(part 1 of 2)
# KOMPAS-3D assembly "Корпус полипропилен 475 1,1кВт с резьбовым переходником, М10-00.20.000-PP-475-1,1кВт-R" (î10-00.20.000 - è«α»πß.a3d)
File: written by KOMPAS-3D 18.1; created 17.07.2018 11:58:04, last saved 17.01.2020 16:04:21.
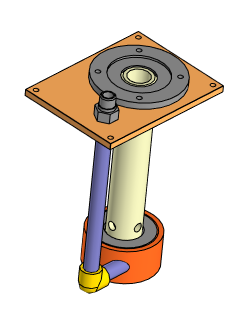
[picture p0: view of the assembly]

Document properties: Автор: Милов; Полное имя файла: C:\Users\User\Desktop\Магна 10 для Караби\М10-00.20.000 - Корпус.a3d

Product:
- Part/product: Корпус полипропилен 475 1,1кВт с резьбовым переходником  | designation М10-00.20.000-PP-475-1,1кВт-R
    Материал: Полипропилен  ГОСТ 26996-86 (density 900 kg/m3)
    Масса: 5.23433
  - Component [detail]: Переходник с пластмассовой резьбой  / наружной 32х1" FV PPR  / ф. "FV PLAST"  | pos. 10  | Масса: 0.0328755; Раздел спецификации: Прочие изделия; source file: D:\1 ПКИ 3D\Полипропиленовые фитинги, трубы\Переходник с пластмассовой резьбой наружной 32х1 FV PPR ф.FV Plast.m3d
  - Component [detail]: Фланец  | designation М10-00.20.002  | pos. 5
      Материал: Полипропилен  ГОСТ 26996-86 (density 900 kg/m3)
      Масса: 0.439491
      Раздел спецификации: Детали
      Форматы листов документа: A3
      Примечание: габ. 71, 80
      source file: М10-00.20.002 - Фланец.cdw, М10-00.20.002 - Фланец.m3d
  - Component [detail]: Колонна  | designation М10-00.25.001-PP-475  | pos. 6  | Масса: 2.126; Раздел спецификации: Детали; Форматы листов документа: A4; source file: М10-00.25.001 - Колонна.m3d
  - Component [detail]: Труба 32 PN10 S=2,9 FV PPR ф. "FV PLAST"  | pos. 12  | Материал: Труба 32 PN10 S=2,9 FV PPR ф. "FV PLAST" (density 0 kg/m3); Раздел спецификации: Материалы; Примечание: мм; source file: Труба 32 PN10 S=2,9 FV PPR ф. FV PLAST.m3d
  - Component [detail]: Колено 90@1~ @2~40FV PPR ф. "FV PLAST"  | pos. 9  | Масса: 0.141726; Раздел спецификации: Прочие изделия; source file: Колено 90гр 32 FV PPR ф. FV PLAST.m3d
  - Component [detail]: Плита опорная  | designation М10-00.20.001-01  | pos. 4  | Масса: 1.84628; Раздел спецификации: Детали; Форматы листов документа: A3; source file: М10-00.20.001 - Плита опорная.m3d
  - Component [assembly]: Обечайка  | designation М10-00.30.000  | pos. 1  | Материал: Полипропилен  ГОСТ 26996-86 (density 900 kg/m3); Масса: 0.647968; Раздел спецификации: Сборочные единицы; Форматы листов документа: A3; source file: М10-00.30.000 - Обечайка.a3d, М10-00.30.000 - Обечайка.cdw
- Part/product: Корпус полипропилен 475 1,1кВт с разъёмной муфтой  | designation М10-00.20.000-PP-475-1,1кВт-M
    Материал: Полипропилен  ГОСТ 26996-86 (density 900 kg/m3)
    Масса: 6.15084
  - Component [detail]: Муфта разъёмная 32  | pos. 7  | Масса: 0.949384; Раздел спецификации: Детали; source file: D:\1 ПКИ 3D\Полипропиленовые фитинги, трубы\Разборные муфты\Муфта разъёмная 32.m3d
  - Component [detail]: Фланец  | designation М10-00.20.002
      Материал: Полипропилен  ГОСТ 26996-86 (density 900 kg/m3)
      Масса: 0.439491
      Раздел спецификации: Детали
      Форматы листов документа: A3
      Примечание: габ. 71, 80
      source file: М10-00.20.002 - Фланец.cdw, М10-00.20.002 - Фланец.m3d
  - Component [detail]: Фланец  | designation М10-00.20.002  | pos. 5
      Материал: Полипропилен  ГОСТ 26996-86 (density 900 kg/m3)
      Масса: 0.439491
      Раздел спецификации: Детали
      Форматы листов документа: A3
      Примечание: габ. 71, 80
      source file: М10-00.20.002 - Фланец.cdw, М10-00.20.002 - Фланец.m3d
  - Component [detail]: Колонна  | designation М10-00.25.001-PP-475  | pos. 6  | Масса: 2.126; Раздел спецификации: Детали; Форматы листов документа: A4; source file: М10-00.25.001 - Колонна.m3d
  - Component [detail]: Труба 32 PN10 S=2,9 FV PPR ф. "FV PLAST"  | pos. 12  | Материал: Труба 32 PN10 S=2,9 FV PPR ф. "FV PLAST" (density 0 kg/m3); Раздел спецификации: Материалы; Примечание: мм; source file: Труба 32 PN10 S=2,9 FV PPR ф. FV PLAST.m3d
  - Component [detail]: Колено 90@1~ @2~40FV PPR ф. "FV PLAST"  | pos. 9  | Масса: 0.141726; Раздел спецификации: Прочие изделия; source file: Колено 90гр 32 FV PPR ф. FV PLAST.m3d
  - Component [detail]: Плита опорная  | designation М10-00.20.001-01  | pos. 4  | Масса: 1.84628; Раздел спецификации: Детали; Форматы листов документа: A3; source file: М10-00.20.001 - Плита опорная.m3d
  - Component [assembly]: Обечайка  | designation М10-00.30.000  | pos. 1  | Материал: Полипропилен  ГОСТ 26996-86 (density 900 kg/m3); Масса: 0.647968; Раздел спецификации: Сборочные единицы; Форматы листов документа: A3; source file: М10-00.30.000 - Обечайка.a3d, М10-00.30.000 - Обечайка.cdw
- Part/product: Корпус полипропилен 475 1,1кВт  | designation М10-00.20.000-PP-475-1,1кВт
    Материал: Полипропилен  ГОСТ 26996-86 (density 900 kg/m3)
    Масса: 5.20146
  - Component [detail]: Фланец  | designation М10-00.20.002  | pos. 361
      Материал: Полипропилен  ГОСТ 26996-86 (density 900 kg/m3)
      Масса: 0.439491
      Раздел спецификации: Детали
      Форматы листов документа: A3
      Примечание: габ. 71, 80
      source file: М10-00.20.002 - Фланец.cdw, М10-00.20.002 - Фланец.m3d
  - Component [assembly]: Обечайка  | designation М10-00.30.000  | pos. 1  | Материал: Полипропилен  ГОСТ 26996-86 (density 900 kg/m3); Масса: 0.647968; Раздел спецификации: Сборочные единицы; Форматы листов документа: A3; source file: М10-00.30.000 - Обечайка.a3d, М10-00.30.000 - Обечайка.cdw
- Part/product: Корпус полипропилен 475 0,75кВт м резьбовым переходником  | designation М10-00.20.000-PP-475-0,75кВт-R
    Материал: Полипропилен  ГОСТ 26996-86 (density 900 kg/m3)
    Масса: 5.23433
  - Component [detail]: Переходник с пластмассовой резьбой  / наружной 32х1" FV PPR  / ф. "FV PLAST"  | pos. 10  | Масса: 0.0328755; Раздел спецификации: Прочие изделия; source file: D:\1 ПКИ 3D\Полипропиленовые фитинги, трубы\Переходник с пластмассовой резьбой наружной 32х1 FV PPR ф.FV Plast.m3d
  - Component [detail]: Фланец  | designation М10-00.20.002
      Материал: Полипропилен  ГОСТ 26996-86 (density 900 kg/m3)
      Масса: 0.439491
      Раздел спецификации: Детали
      Форматы листов документа: A3
      Примечание: габ. 71, 80
      source file: М10-00.20.002 - Фланец.cdw, М10-00.20.002 - Фланец.m3d
  - Component [detail]: Фланец  | designation М10-00.20.002  | pos. 5
      Материал: Полипропилен  ГОСТ 26996-86 (density 900 kg/m3)
      Масса: 0.439491
      Раздел спецификации: Детали
      Форматы листов документа: A3
      Примечание: габ. 71, 80
      source file: М10-00.20.002 - Фланец.cdw, М10-00.20.002 - Фланец.m3d
  - Component [detail]: Колонна  | designation М10-00.25.001-PP-475  | pos. 6  | Масса: 2.126; Раздел спецификации: Детали; Форматы листов документа: A4; source file: М10-00.25.001 - Колонна.m3d
  - Component [detail]: Труба 32 PN10 S=2,9 FV PPR ф. "FV PLAST"  | pos. 12  | Материал: Труба 32 PN10 S=2,9 FV PPR ф. "FV PLAST" (density 0 kg/m3); Раздел спецификации: Материалы; Примечание: мм; source file: Труба 32 PN10 S=2,9 FV PPR ф. FV PLAST.m3d
  - Component [detail]: Колено 90@1~ @2~40FV PPR ф. "FV PLAST"  | pos. 9  | Масса: 0.141726; Раздел спецификации: Прочие изделия; source file: Колено 90гр 32 FV PPR ф. FV PLAST.m3d
  - Component [detail]: Плита опорная  | designation М10-00.20.001-01  | pos. 4  | Масса: 1.84628; Раздел спецификации: Детали; Форматы листов документа: A3; source file: М10-00.20.001 - Плита опорная.m3d
  - Component [assembly]: Обечайка  | designation М10-00.30.000  | pos. 1  | Материал: Полипропилен  ГОСТ 26996-86 (density 900 kg/m3); Масса: 0.647968; Раздел спецификации: Сборочные единицы; Форматы листов документа: A3; source file: М10-00.30.000 - Обечайка.a3d, М10-00.30.000 - Обечайка.cdw
- Part/product: Корпус полипропилен 475 0,75кВт с разъёмной муфтой  | designation М10-00.20.000-PP-475-0,75кВт-M
    Материал: Полипропилен  ГОСТ 26996-86 (density 900 kg/m3)
    Масса: 6.15084
  - Component [detail]: Фланец  | designation М10-00.20.002
      Материал: Полипропилен  ГОСТ 26996-86 (density 900 kg/m3)
      Масса: 0.439491
      Раздел спецификации: Детали
      Форматы листов документа: A3
      Примечание: габ. 71, 80
      source file: М10-00.20.002 - Фланец.cdw, М10-00.20.002 - Фланец.m3d
  - Component [detail]: Фланец  | designation М10-00.20.002  | pos. 5
      Материал: Полипропилен  ГОСТ 26996-86 (density 900 kg/m3)
      Масса: 0.439491
      Раздел спецификации: Детали
      Форматы листов документа: A3
      Примечание: габ. 71, 80
      source file: М10-00.20.002 - Фланец.cdw, М10-00.20.002 - Фланец.m3d
  - Component [detail]: Муфта разъёмная 32  | pos. 7  | Масса: 0.949384; Раздел спецификации: Детали; source file: D:\1 ПКИ 3D\Полипропиленовые фитинги, трубы\Разборные муфты\Муфта разъёмная 32.m3d
  - Component [detail]: Колонна  | designation М10-00.25.001-PP-475  | pos. 6  | Масса: 2.126; Раздел спецификации: Детали; Форматы листов документа: A4; source file: М10-00.25.001 - Колонна.m3d
  - Component [detail]: Труба 32 PN10 S=2,9 FV PPR ф. "FV PLAST"  | pos. 12  | Материал: Труба 32 PN10 S=2,9 FV PPR ф. "FV PLAST" (density 0 kg/m3); Раздел спецификации: Материалы; Примечание: мм; source file: Труба 32 PN10 S=2,9 FV PPR ф. FV PLAST.m3d
  - Component [detail]: Колено 90@1~ @2~40FV PPR ф. "FV PLAST"  | pos. 9  | Масса: 0.141726; Раздел спецификации: Прочие изделия; source file: Колено 90гр 32 FV PPR ф. FV PLAST.m3d
  - Component [detail]: Плита опорная  | designation М10-00.20.001-01  | pos. 4  | Масса: 1.84628; Раздел спецификации: Детали; Форматы листов документа: A3; source file: М10-00.20.001 - Плита опорная.m3d
  - Component [assembly]: Обечайка  | designation М10-00.30.000  | pos. 1  | Материал: Полипропилен  ГОСТ 26996-86 (density 900 kg/m3); Масса: 0.647968; Раздел спецификации: Сборочные единицы; Форматы листов документа: A3; source file: М10-00.30.000 - Обечайка.a3d, М10-00.30.000 - Обечайка.cdw
- Part/product: Корпус полипропилен 475 0,75кВт  | designation М10-00.20.000-PP-475-0,75кВт
    Материал: Полипропилен  ГОСТ 26996-86 (density 900 kg/m3)
    Масса: 5.20146
  - Component [detail]: Фланец  | designation М10-00.20.002  | pos. 347
      Материал: Полипропилен  ГОСТ 26996-86 (density 900 kg/m3)
      Масса: 0.439491
      Раздел спецификации: Детали
      Форматы листов документа: A3
      Примечание: габ. 71, 80
      source file: М10-00.20.002 - Фланец.cdw, М10-00.20.002 - Фланец.m3d
  - Component [assembly]: Обечайка  | designation М10-00.30.000  | pos. 1  | Материал: Полипропилен  ГОСТ 26996-86 (density 900 kg/m3); Масса: 0.647968; Раздел спецификации: Сборочные единицы; Форматы листов документа: A3; source file: М10-00.30.000 - Обечайка.a3d, М10-00.30.000 - Обечайка.cdw
- Part/product: Корпус полипропилен 475 0,55кВт с резьбовым переходником  | designation М10-00.20.000-PP-475-0,55кВт-R
    Материал: Полипропилен  ГОСТ 26996-86 (density 900 kg/m3)
    Масса: 5.49071
  - Component [detail]: Колонна  | designation М10-00.25.001-PP-475  | pos. 6  | Масса: 2.126; Раздел спецификации: Детали; Форматы листов документа: A4; source file: М10-00.25.001 - Колонна.m3d
  - Component [detail]: Труба 32 PN10 S=2,9 FV PPR ф. "FV PLAST"  | pos. 12  | Материал: Труба 32 PN10 S=2,9 FV PPR ф. "FV PLAST" (density 0 kg/m3); Раздел спецификации: Материалы; Примечание: мм; source file: Труба 32 PN10 S=2,9 FV PPR ф. FV PLAST.m3d
  - Component [detail]: Колено 90@1~ @2~40FV PPR ф. "FV PLAST"  | pos. 9  | Масса: 0.141726; Раздел спецификации: Прочие изделия; source file: Колено 90гр 32 FV PPR ф. FV PLAST.m3d
  - Component [detail]: Плита опорная  | designation М10-00.20.001  | pos. 5  | Масса: 2.06392; Раздел спецификации: Детали; Форматы листов документа: A3; source file: М10-00.20.001 - Плита опорная.m3d
  - Component [detail]: Фланец  | designation М5-00.10.002  | pos. 4  | Масса: 0.478225; Раздел спецификации: Детали; Форматы листов документа: A4; source file: D:\Magna\Магна Ins\Магна ins 5\М5-00.00.000 - Насос Магна ins 5-C-N\3Д модель\..\Чертежи\М5-00.10.002 - Фланец.cdw, D:\Magna\Магна Ins\Магна ins 5\М5-00.00.000 - Насос Магна ins 5-C-N\3Д модель\М5-00.10.002 - Фланец.m3d
  - Component [assembly]: Обечайка  | designation М10-00.30.000  | pos. 1  | Материал: Полипропилен  ГОСТ 26996-86 (density 900 kg/m3); Масса: 0.647968; Раздел спецификации: Сборочные единицы; Форматы листов документа: A3; source file: М10-00.30.000 - Обечайка.a3d, М10-00.30.000 - Обечайка.cdw
  - Component [detail]: Переходник с пластмассовой резьбой  / наружной 32х1" FV PPR  / ф. "FV PLAST"  | pos. 10  | Масса: 0.0328755; Раздел спецификации: Прочие изделия; source file: D:\1 ПКИ 3D\Полипропиленовые фитинги, трубы\Переходник с пластмассовой резьбой наружной 32х1 FV PPR ф.FV Plast.m3d
- Part/product: Корпус полипропилен 475 0,55кВт с разъёмной муфтой  | designation М10-00.20.000-PP-475-0,55кВт-M
    Материал: Полипропилен  ГОСТ 26996-86 (density 900 kg/m3)
    Масса: 6.40722
  - Component [detail]: Колонна  | designation М10-00.25.001-PP-475  | pos. 6  | Масса: 2.126; Раздел спецификации: Детали; Форматы листов документа: A4; source file: М10-00.25.001 - Колонна.m3d
  - Component [detail]: Труба 32 PN10 S=2,9 FV PPR ф. "FV PLAST"  | pos. 12  | Материал: Труба 32 PN10 S=2,9 FV PPR ф. "FV PLAST" (density 0 kg/m3); Раздел спецификации: Материалы; Примечание: мм; source file: Труба 32 PN10 S=2,9 FV PPR ф. FV PLAST.m3d
  - Component [detail]: Колено 90@1~ @2~40FV PPR ф. "FV PLAST"  | pos. 9  | Масса: 0.141726; Раздел спецификации: Прочие изделия; source file: Колено 90гр 32 FV PPR ф. FV PLAST.m3d
  - Component [detail]: Плита опорная  | designation М10-00.20.001  | pos. 5  | Масса: 2.06392; Раздел спецификации: Детали; Форматы листов документа: A3; source file: М10-00.20.001 - Плита опорная.m3d
  - Component [detail]: Фланец  | designation М5-00.10.002  | pos. 4  | Масса: 0.478225; Раздел спецификации: Детали; Форматы листов документа: A4; source file: D:\Magna\Магна Ins\Магна ins 5\М5-00.00.000 - Насос Магна ins 5-C-N\3Д модель\..\Чертежи\М5-00.10.002 - Фланец.cdw, D:\Magna\Магна Ins\Магна ins 5\М5-00.00.000 - Насос Магна ins 5-C-N\3Д модель\М5-00.10.002 - Фланец.m3d
  - Component [assembly]: Обечайка  | designation М10-00.30.000  | pos. 1  | Материал: Полипропилен  ГОСТ 26996-86 (density 900 kg/m3); Масса: 0.647968; Раздел спецификации: Сборочные единицы; Форматы листов документа: A3; source file: М10-00.30.000 - Обечайка.a3d, М10-00.30.000 - Обечайка.cdw
  - Component [detail]: Муфта разъёмная 32  | pos. 7  | Масса: 0.949384; Раздел спецификации: Детали; source file: D:\1 ПКИ 3D\Полипропиленовые фитинги, трубы\Разборные муфты\Муфта разъёмная 32.m3d
- Part/product: Корпус полипропилен 475 0,55кВт  | designation М10-00.20.000-PP-475-0,55кВт
    Материал: Полипропилен  ГОСТ 26996-86 (density 900 kg/m3)
    Масса: 5.44547
  - Component [assembly]: Обечайка  | designation М10-00.30.000  | pos. 1  | Материал: Полипропилен  ГОСТ 26996-86 (density 900 kg/m3); Масса: 0.647968; Раздел спецификации: Сборочные единицы; Форматы листов документа: A3; source file: М10-00.30.000 - Обечайка.a3d, М10-00.30.000 - Обечайка.cdw
  - Component [detail]: Фланец  | designation М5-00.10.002  | pos. 4  | Масса: 0.478225; Раздел спецификации: Детали; Форматы листов документа: A4; source file: D:\Magna\Магна Ins\Магна ins 5\М5-00.00.000 - Насос Магна ins 5-C-N\3Д модель\..\Чертежи\М5-00.10.002 - Фланец.cdw, D:\Magna\Магна Ins\Магна ins 5\М5-00.00.000 - Насос Магна ins 5-C-N\3Д модель\М5-00.10.002 - Фланец.m3d
- Part/product: Корпус полипропилен 425 0,75кВт с резьбовым переходником  | designation М10-00.20.000-PP-425-0,75кВт-R
    Материал: Полипропилен  ГОСТ 26996-86 (density 900 kg/m3)
    Масса: 4.98891
  - Component [detail]: Переходник с пластмассовой резьбой  / наружной 32х1" FV PPR  / ф. "FV PLAST"  | pos. 10  | Масса: 0.0328755; Раздел спецификации: Прочие изделия; source file: D:\1 ПКИ 3D\Полипропиленовые фитинги, трубы\Переходник с пластмассовой резьбой наружной 32х1 FV PPR ф.FV Plast.m3d
  - Component [detail]: Фланец  | designation М10-00.20.002  | pos. 5
      Материал: Полипропилен  ГОСТ 26996-86 (density 900 kg/m3)
      Масса: 0.439491
      Раздел спецификации: Детали
      Форматы листов документа: A3
      Примечание: габ. 71, 80
      source file: М10-00.20.002 - Фланец.cdw, М10-00.20.002 - Фланец.m3d
  - Component [detail]: Колонна  | designation М10-00.25.001-PP-425  | pos. 6  | Масса: 1.88058; Раздел спецификации: Детали; Форматы листов документа: A4; source file: М10-00.25.001 - Колонна.m3d
  - Component [detail]: Труба 32 PN10 S=2,9 FV PPR ф. "FV PLAST"  | pos. 12  | Материал: Труба 32 PN10 S=2,9 FV PPR ф. "FV PLAST" (density 0 kg/m3); Раздел спецификации: Материалы; Примечание: мм; source file: Труба 32 PN10 S=2,9 FV PPR ф. FV PLAST.m3d
  - Component [detail]: Колено 90@1~ @2~40FV PPR ф. "FV PLAST"  | pos. 9  | Масса: 0.141726; Раздел спецификации: Прочие изделия; source file: Колено 90гр 32 FV PPR ф. FV PLAST.m3d
  - Component [detail]: Плита опорная  | designation М10-00.20.001-01  | pos. 4  | Масса: 1.84628; Раздел спецификации: Детали; Форматы листов документа: A3; source file: М10-00.20.001 - Плита опорная.m3d
  - Component [assembly]: Обечайка  | designation М10-00.30.000  | pos. 1  | Материал: Полипропилен  ГОСТ 26996-86 (density 900 kg/m3); Масса: 0.647968; Раздел спецификации: Сборочные единицы; Форматы листов документа: A3; source file: М10-00.30.000 - Обечайка.a3d, М10-00.30.000 - Обечайка.cdw
- Part/product: Корпус полипропилен 425 0,75кВт с разъёмной муфтой  | designation М10-00.20.000-PP-425-0,75кВт-M
    Материал: Полипропилен  ГОСТ 26996-86 (density 900 kg/m3)
    Масса: 5.90542
  - Component [detail]: Муфта разъёмная 32  | pos. 7  | Масса: 0.949384; Раздел спецификации: Детали; source file: D:\1 ПКИ 3D\Полипропиленовые фитинги, трубы\Разборные муфты\Муфта разъёмная 32.m3d
  - Component [detail]: Фланец  | designation М10-00.20.002  | pos. 5
      Материал: Полипропилен  ГОСТ 26996-86 (density 900 kg/m3)
      Масса: 0.439491
      Раздел спецификации: Детали
      Форматы листов документа: A3
      Примечание: габ. 71, 80
      source file: М10-00.20.002 - Фланец.cdw, М10-00.20.002 - Фланец.m3d
  - Component [detail]: Колонна  | designation М10-00.25.001-PP-425  | pos. 6  | Масса: 1.88058; Раздел спецификации: Детали; Форматы листов документа: A4; source file: М10-00.25.001 - Колонна.m3d
  - Component [detail]: Труба 32 PN10 S=2,9 FV PPR ф. "FV PLAST"  | pos. 12  | Материал: Труба 32 PN10 S=2,9 FV PPR ф. "FV PLAST" (density 0 kg/m3); Раздел спецификации: Материалы; Примечание: мм; source file: Труба 32 PN10 S=2,9 FV PPR ф. FV PLAST.m3d
  - Component [detail]: Колено 90@1~ @2~40FV PPR ф. "FV PLAST"  | pos. 9  | Масса: 0.141726; Раздел спецификации: Прочие изделия; source file: Колено 90гр 32 FV PPR ф. FV PLAST.m3d
  - Component [detail]: Плита опорная  | designation М10-00.20.001-01  | pos. 4  | Масса: 1.84628; Раздел спецификации: Детали; Форматы листов документа: A3; source file: М10-00.20.001 - Плита опорная.m3d
  - Component [assembly]: Обечайка  | designation М10-00.30.000  | pos. 1  | Материал: Полипропилен  ГОСТ 26996-86 (density 900 kg/m3); Масса: 0.647968; Раздел спецификации: Сборочные единицы; Форматы листов документа: A3; source file: М10-00.30.000 - Обечайка.a3d, М10-00.30.000 - Обечайка.cdw
- Part/product: Корпус полипропилен 375 1,1кВт с разъёмной муфтой  | designation М10-00.20.000-PP-375-1,1кВт-M
    Материал: Полипропилен  ГОСТ 26996-86 (density 900 kg/m3)
    Масса: 5.65999
  - Component [detail]: Муфта разъёмная 32  | pos. 7  | Масса: 0.949384; Раздел спецификации: Детали; source file: D:\1 ПКИ 3D\Полипропиленовые фитинги, трубы\Разборные муфты\Муфта разъёмная 32.m3d
  - Component [detail]: Колонна  | designation М10-00.25.001-PP-375  | pos. 6  | Масса: 1.63515; Раздел спецификации: Детали; Форматы листов документа: A4; source file: М10-00.25.001 - Колонна.m3d
  - Component [detail]: Труба 32 PN10 S=2,9 FV PPR ф. "FV PLAST"  | pos. 12  | Материал: Труба 32 PN10 S=2,9 FV PPR ф. "FV PLAST" (density 0 kg/m3); Раздел спецификации: Материалы; Примечание: мм; source file: Труба 32 PN10 S=2,9 FV PPR ф. FV PLAST.m3d
  - Component [detail]: Колено 90@1~ @2~40FV PPR ф. "FV PLAST"  | pos. 9  | Масса: 0.141726; Раздел спецификации: Прочие изделия; source file: Колено 90гр 32 FV PPR ф. FV PLAST.m3d
  - Component [detail]: Плита опорная  | designation М10-00.20.001-01  | pos. 4  | Масса: 1.84628; Раздел спецификации: Детали; Форматы листов документа: A3; source file: М10-00.20.001 - Плита опорная.m3d
  - Component [assembly]: Обечайка  | designation М10-00.30.000  | pos. 1  | Материал: Полипропилен  ГОСТ 26996-86 (density 900 kg/m3); Масса: 0.647968; Раздел спецификации: Сборочные единицы; Форматы листов документа: A3; source file: М10-00.30.000 - Обечайка.a3d, М10-00.30.000 - Обечайка.cdw
  - Component [detail]: Фланец  | designation М10-00.20.002  | pos. 5
      Материал: Полипропилен  ГОСТ 26996-86 (density 900 kg/m3)
      Масса: 0.439491
      Раздел спецификации: Детали
      Форматы листов документа: A3
      Примечание: габ. 71, 80
      source file: М10-00.20.002 - Фланец.cdw, М10-00.20.002 - Фланец.m3d
- Part/product: Корпус полипропилен 375 1,1кВт с резьбовым переходником  | designation М10-00.20.000-PP-375-1,1кВт-R
    Материал: Полипропилен  ГОСТ 26996-86 (density 900 kg/m3)
    Масса: 4.74348
  - Component [detail]: Фланец  | designation М10-00.20.002
      Материал: Полипропилен  ГОСТ 26996-86 (density 900 kg/m3)
      Масса: 0.439491
      Раздел спецификации: Детали
      Форматы листов документа: A3
      Примечание: габ. 71, 80
      source file: М10-00.20.002 - Фланец.cdw, М10-00.20.002 - Фланец.m3d
  - Component [detail]: Фланец  | designation М10-00.20.002  | pos. 5
      Материал: Полипропилен  ГОСТ 26996-86 (density 900 kg/m3)
      Масса: 0.439491
      Раздел спецификации: Детали
      Форматы листов документа: A3
      Примечание: габ. 71, 80
      source file: М10-00.20.002 - Фланец.cdw, М10-00.20.002 - Фланец.m3d
  - Component [detail]: Колонна  | designation М10-00.25.001-PP-375  | pos. 6  | Масса: 1.63515; Раздел спецификации: Детали; Форматы листов документа: A4; source file: М10-00.25.001 - Колонна.m3d
  - Component [detail]: Труба 32 PN10 S=2,9 FV PPR ф. "FV PLAST"  | pos. 12  | Материал: Труба 32 PN10 S=2,9 FV PPR ф. "FV PLAST" (density 0 kg/m3); Раздел спецификации: Материалы; Примечание: мм; source file: Труба 32 PN10 S=2,9 FV PPR ф. FV PLAST.m3d
  - Component [detail]: Колено 90@1~ @2~40FV PPR ф. "FV PLAST"  | pos. 9  | Масса: 0.141726; Раздел спецификации: Прочие изделия; source file: Колено 90гр 32 FV PPR ф. FV PLAST.m3d
  - Component [detail]: Плита опорная  | designation М10-00.20.001-01  | pos. 4  | Масса: 1.84628; Раздел спецификации: Детали; Форматы листов документа: A3; source file: М10-00.20.001 - Плита опорная.m3d
  - Component [assembly]: Обечайка  | designation М10-00.30.000  | pos. 1  | Материал: Полипропилен  ГОСТ 26996-86 (density 900 kg/m3); Масса: 0.647968; Раздел спецификации: Сборочные единицы; Форматы листов документа: A3; source file: М10-00.30.000 - Обечайка.a3d, М10-00.30.000 - Обечайка.cdw
  - Component [detail]: Переходник с пластмассовой резьбой  / наружной 32х1" FV PPR  / ф. "FV PLAST"  | pos. 10  | Масса: 0.0328755; Раздел спецификации: Прочие изделия; source file: D:\1 ПКИ 3D\Полипропиленовые фитинги, трубы\Переходник с пластмассовой резьбой наружной 32х1 FV PPR ф.FV Plast.m3d
- Part/product: Корпус полипропилен 375 0,75кВт с резьбовым переходником  | designation М10-00.20.000-PP-375-0,75кВт-R
    Материал: Полипропилен  ГОСТ 26996-86 (density 900 kg/m3)
    Масса: 4.74348
  - Component [detail]: Переходник с пластмассовой резьбой  / наружной 32х1" FV PPR  / ф. "FV PLAST"  | pos. 10  | Масса: 0.0328755; Раздел спецификации: Прочие изделия; source file: D:\1 ПКИ 3D\Полипропиленовые фитинги, трубы\Переходник с пластмассовой резьбой наружной 32х1 FV PPR ф.FV Plast.m3d
  - Component [detail]: Колонна  | designation М10-00.25.001-PP-375  | pos. 6  | Масса: 1.63515; Раздел спецификации: Детали; Форматы листов документа: A4; source file: М10-00.25.001 - Колонна.m3d
  - Component [detail]: Труба 32 PN10 S=2,9 FV PPR ф. "FV PLAST"  | pos. 12  | Материал: Труба 32 PN10 S=2,9 FV PPR ф. "FV PLAST" (density 0 kg/m3); Раздел спецификации: Материалы; Примечание: мм; source file: Труба 32 PN10 S=2,9 FV PPR ф. FV PLAST.m3d
  - Component [detail]: Колено 90@1~ @2~40FV PPR ф. "FV PLAST"  | pos. 9  | Масса: 0.141726; Раздел спецификации: Прочие изделия; source file: Колено 90гр 32 FV PPR ф. FV PLAST.m3d
  - Component [detail]: Плита опорная  | designation М10-00.20.001-01  | pos. 4  | Масса: 1.84628; Раздел спецификации: Детали; Форматы листов документа: A3; source file: М10-00.20.001 - Плита опорная.m3d
  - Component [assembly]: Обечайка  | designation М10-00.30.000  | pos. 1  | Материал: Полипропилен  ГОСТ 26996-86 (density 900 kg/m3); Масса: 0.647968; Раздел спецификации: Сборочные единицы; Форматы листов документа: A3; source file: М10-00.30.000 - Обечайка.a3d, М10-00.30.000 - Обечайка.cdw
  - Component [detail]: Фланец  | designation М10-00.20.002  | pos. 5
      Материал: Полипропилен  ГОСТ 26996-86 (density 900 kg/m3)
      Масса: 0.439491
      Раздел спецификации: Детали
      Форматы листов документа: A3
      Примечание: габ. 71, 80
      source file: М10-00.20.002 - Фланец.cdw, М10-00.20.002 - Фланец.m3d
- Part/product: Корпус полипропилен 375 0,75кВт  | designation М10-00.20.000-PP-375-0,75кВт
    Материал: Полипропилен  ГОСТ 26996-86 (density 900 kg/m3)
    Масса: 4.71061
  - Component [detail]: Фланец  | designation М10-00.20.002  | pos. 5
      Материал: Полипропилен  ГОСТ 26996-86 (density 900 kg/m3)
      Масса: 0.439491
      Раздел спецификации: Детали
      Форматы листов документа: A3
      Примечание: габ. 71, 80
      source file: М10-00.20.002 - Фланец.cdw, М10-00.20.002 - Фланец.m3d
  - Component [assembly]: Обечайка  | designation М10-00.30.000  | pos. 1  | Материал: Полипропилен  ГОСТ 26996-86 (density 900 kg/m3); Масса: 0.647968; Раздел спецификации: Сборочные единицы; Форматы листов документа: A3; source file: М10-00.30.000 - Обечайка.a3d, М10-00.30.000 - Обечайка.cdw
- Part/product: Корпус полипропилен 375 0,55 кВт с разъёмной муфтой  | designation М10-00.20.000-PP-375-0,55кВт-M
    Материал: Полипропилен  ГОСТ 26996-86 (density 900 kg/m3)
    Масса: 5.91637
  - Component [detail]: Муфта разъёмная 32  | pos. 7  | Масса: 0.949384; Раздел спецификации: Детали; source file: D:\1 ПКИ 3D\Полипропиленовые фитинги, трубы\Разборные муфты\Муфта разъёмная 32.m3d
  - Component [detail]: Колонна  | designation М10-00.25.001-PP-375  | pos. 6  | Масса: 1.63515; Раздел спецификации: Детали; Форматы листов документа: A4; source file: М10-00.25.001 - Колонна.m3d
  - Component [detail]: Труба 32 PN10 S=2,9 FV PPR ф. "FV PLAST"  | pos. 12  | Материал: Труба 32 PN10 S=2,9 FV PPR ф. "FV PLAST" (density 0 kg/m3); Раздел спецификации: Материалы; Примечание: мм; source file: Труба 32 PN10 S=2,9 FV PPR ф. FV PLAST.m3d
  - Component [detail]: Колено 90@1~ @2~40FV PPR ф. "FV PLAST"  | pos. 9  | Масса: 0.141726; Раздел спецификации: Прочие изделия; source file: Колено 90гр 32 FV PPR ф. FV PLAST.m3d
  - Component [detail]: Плита опорная  | designation М10-00.20.001  | pos. 5  | Масса: 2.06392; Раздел спецификации: Детали; Форматы листов документа: A3; source file: М10-00.20.001 - Плита опорная.m3d
  - Component [detail]: Фланец  | designation М5-00.10.002  | pos. 4  | Масса: 0.478225; Раздел спецификации: Детали; Форматы листов документа: A4; source file: D:\Magna\Магна Ins\Магна ins 5\М5-00.00.000 - Насос Магна ins 5-C-N\3Д модель\..\Чертежи\М5-00.10.002 - Фланец.cdw, D:\Magna\Магна Ins\Магна ins 5\М5-00.00.000 - Насос Магна ins 5-C-N\3Д модель\М5-00.10.002 - Фланец.m3d
  - Component [assembly]: Обечайка  | designation М10-00.30.000  | pos. 1  | Материал: Полипропилен  ГОСТ 26996-86 (density 900 kg/m3); Масса: 0.647968; Раздел спецификации: Сборочные единицы; Форматы листов документа: A3; source file: М10-00.30.000 - Обечайка.a3d, М10-00.30.000 - Обечайка.cdw
- Part/product: Корпус полипропилен 375 0,55 кВт с резьбовым переходником  | designation М10-00.20.000-PP-375-0,55кВт-R
    Материал: Полипропилен  ГОСТ 26996-86 (density 900 kg/m3)
    Масса: 4.99986
  - Component [detail]: Переходник с пластмассовой резьбой  / наружной 32х1" FV PPR  / ф. "FV PLAST"  | pos. 10  | Масса: 0.0328755; Раздел спецификации: Прочие изделия; source file: D:\1 ПКИ 3D\Полипропиленовые фитинги, трубы\Переходник с пластмассовой резьбой наружной 32х1 FV PPR ф.FV Plast.m3d
  - Component [detail]: Колонна  | designation М10-00.25.001-PP-375  | pos. 6  | Масса: 1.63515; Раздел спецификации: Детали; Форматы листов документа: A4; source file: М10-00.25.001 - Колонна.m3d
  - Component [detail]: Труба 32 PN10 S=2,9 FV PPR ф. "FV PLAST"  | pos. 12  | Материал: Труба 32 PN10 S=2,9 FV PPR ф. "FV PLAST" (density 0 kg/m3); Раздел спецификации: Материалы; Примечание: мм; source file: Труба 32 PN10 S=2,9 FV PPR ф. FV PLAST.m3d
  - Component [detail]: Колено 90@1~ @2~40FV PPR ф. "FV PLAST"  | pos. 9  | Масса: 0.141726; Раздел спецификации: Прочие изделия; source file: Колено 90гр 32 FV PPR ф. FV PLAST.m3d
  - Component [detail]: Плита опорная  | designation М10-00.20.001  | pos. 5  | Масса: 2.06392; Раздел спецификации: Детали; Форматы листов документа: A3; source file: М10-00.20.001 - Плита опорная.m3d
  - Component [detail]: Фланец  | designation М5-00.10.002  | pos. 4  | Масса: 0.478225; Раздел спецификации: Детали; Форматы листов документа: A4; source file: D:\Magna\Магна Ins\Магна ins 5\М5-00.00.000 - Насос Магна ins 5-C-N\3Д модель\..\Чертежи\М5-00.10.002 - Фланец.cdw, D:\Magna\Магна Ins\Магна ins 5\М5-00.00.000 - Насос Магна ins 5-C-N\3Д модель\М5-00.10.002 - Фланец.m3d
  - Component [assembly]: Обечайка  | designation М10-00.30.000  | pos. 1  | Материал: Полипропилен  ГОСТ 26996-86 (density 900 kg/m3); Масса: 0.647968; Раздел спецификации: Сборочные единицы; Форматы листов документа: A3; source file: М10-00.30.000 - Обечайка.a3d, М10-00.30.000 - Обечайка.cdw
- Part/product: Корпус полипропилен 375 0,55 кВт  | designation М10-00.20.000-PP-375-0,55кВт
    Материал: Полипропилен  ГОСТ 26996-86 (density 900 kg/m3)
    Масса: 4.96698
  - Component [assembly]: Обечайка  | designation М10-00.30.000  | pos. 1  | Материал: Полипропилен  ГОСТ 26996-86 (density 900 kg/m3); Масса: 0.647968; Раздел спецификации: Сборочные единицы; Форматы листов документа: A3; source file: М10-00.30.000 - Обечайка.a3d, М10-00.30.000 - Обечайка.cdw
  - Component [detail]: Фланец  | designation М5-00.10.002  | pos. 4  | Масса: 0.478225; Раздел спецификации: Детали; Форматы листов документа: A4; source file: D:\Magna\Магна Ins\Магна ins 5\М5-00.00.000 - Насос Магна ins 5-C-N\3Д модель\..\Чертежи\М5-00.10.002 - Фланец.cdw, D:\Magna\Магна Ins\Магна ins 5\М5-00.00.000 - Насос Магна ins 5-C-N\3Д модель\М5-00.10.002 - Фланец.m3d
- Part/product: Корпус полипропилен  | designation М10-00.20.000-PP-475
    Материал: Полипропилен  ГОСТ 26996-86 (density 900 kg/m3)
    Масса: 5.45783
  - Component [detail]: Фланец  | designation М5-00.10.002  | pos. 4  | Масса: 0.478225; Раздел спецификации: Детали; Форматы листов документа: A4; source file: D:\Magna\Магна Ins\Магна ins 5\М5-00.00.000 - Насос Магна ins 5-C-N\3Д модель\..\Чертежи\М5-00.10.002 - Фланец.cdw, D:\Magna\Магна Ins\Магна ins 5\М5-00.00.000 - Насос Магна ins 5-C-N\3Д модель\М5-00.10.002 - Фланец.m3d
  - Component [assembly]: Обечайка  | designation М10-00.30.000  | pos. 1  | Материал: Полипропилен  ГОСТ 26996-86 (density 900 kg/m3); Масса: 0.647968; Раздел спецификации: Сборочные единицы; Форматы листов документа: A3; source file: М10-00.30.000 - Обечайка.a3d, М10-00.30.000 - Обечайка.cdw
- Part/product: Корпус полипропилен 425  | designation М10-00.20.000-PP-425
    Материал: Полипропилен  ГОСТ 26996-86 (density 900 kg/m3)
    Масса: 5.21242
  - Component [detail]: Фланец  | designation М5-00.10.002  | pos. 4  | Масса: 0.478225; Раздел спецификации: Детали; Форматы листов документа: A4; source file: D:\Magna\Магна Ins\Магна ins 5\М5-00.00.000 - Насос Магна ins 5-C-N\3Д модель\..\Чертежи\М5-00.10.002 - Фланец.cdw, D:\Magna\Магна Ins\Магна ins 5\М5-00.00.000 - Насос Магна ins 5-C-N\3Д модель\М5-00.10.002 - Фланец.m3d
  - Component [assembly]: Обечайка  | designation М10-00.30.000  | pos. 1  | Материал: Полипропилен  ГОСТ 26996-86 (density 900 kg/m3); Масса: 0.647968; Раздел спецификации: Сборочные единицы; Форматы листов документа: A3; source file: М10-00.30.000 - Обечайка.a3d, М10-00.30.000 - Обечайка.cdw
- Part/product: Корпус полипропилен 375  | designation М10-00.20.000-PP-375
    Материал: Полипропилен  ГОСТ 26996-86 (density 900 kg/m3)
    Масса: 4.95462
  - Component [detail]: Колонна  | designation М10-00.25.001-PP-375  | pos. 6  | Масса: 1.63515; Раздел спецификации: Детали; Форматы листов документа: A4; source file: М10-00.25.001 - Колонна.m3d
  - Component [detail]: Фланец  | designation М5-00.10.002  | pos. 4  | Масса: 0.478225; Раздел спецификации: Детали; Форматы листов документа: A4; source file: D:\Magna\Магна Ins\Магна ins 5\М5-00.00.000 - Насос Магна ins 5-C-N\3Д модель\..\Чертежи\М5-00.10.002 - Фланец.cdw, D:\Magna\Магна Ins\Магна ins 5\М5-00.00.000 - Насос Магна ins 5-C-N\3Д модель\М5-00.10.002 - Фланец.m3d
  - Component [assembly]: Обечайка  | designation М10-00.30.000  | pos. 1  | Материал: Полипропилен  ГОСТ 26996-86 (density 900 kg/m3); Масса: 0.647968; Раздел спецификации: Сборочные единицы; Форматы листов документа: A3; source file: М10-00.30.000 - Обечайка.a3d, М10-00.30.000 - Обечайка.cdw
- Part/product: Корпус  | designation М10-00.20.000
    Материал: Полипропилен  ГОСТ 26996-86 (density 900 kg/m3)
    Масса: 4.96916
    source file: М10-00.20.000 - Корпус.cdw
  - Component [detail]: Колонна  | designation М10-00.25.001-PP  | pos. 6  | Масса: 1.63515; Раздел спецификации: Детали; Форматы листов документа: A4; source file: М10-00.25.001 - Колонна.cdw, М10-00.25.001 - Колонна.m3d
  - Component [detail]: Труба 32 PN10 S=2,9 FV PPR ф. "FV PLAST"  | pos. 12  | Материал: Труба 32 PN10 S=2,9 FV PPR ф. "FV PLAST" (density 0 kg/m3); Раздел спецификации: Материалы; Примечание: мм; source file: Труба 32 PN10 S=2,9 FV PPR ф. FV PLAST.m3d
  - Component [detail]: Колено 90@1~ @2~40FV PPR ф. "FV PLAST"  | pos. 9  | Масса: 0.141726; Раздел спецификации: Прочие изделия; source file: Колено 90гр 32 FV PPR ф. FV PLAST.m3d
  - Component [detail]: Плита опорная  | designation М10-00.20.001  | pos. 5  | Масса: 2.06392; Раздел спецификации: Детали; Форматы листов документа: A3; source file: М10-00.20.001 - Плита опорная.m3d
  - Component [detail]: Фланец  | designation М5-00.10.002  | pos. 4  | Масса: 0.478225; Раздел спецификации: Детали; Форматы листов документа: A4; source file: ..\..\..\Магна ins 5\М5-00.00.000 - Насос Магна ins 5-C-N\3Д модель\М5-00.10.002 - Фланец.m3d, ..\..\..\Магна ins 5\М5-00.00.000 - Насос Магна ins 5-C-N\Чертежи\М5-00.10.002 - Фланец.cdw, D:\Magna\Магна Ins\Магна ins 5\М5-00.00.000 - Насос Магна ins 5-C-N\3Д модель\М5-00.10.002 - Фланец.m3d
  - Component [assembly]: Обечайка  | designation М10-00.30.000  | pos. 1  | Материал: Полипропилен  ГОСТ 26996-86 (density 900 kg/m3); Масса: 0.647968; Раздел спецификации: Сборочные единицы; Форматы листов документа: A3; source file: М10-00.30.000 - Обечайка.a3d, М10-00.30.000 - Обечайка.cdw
- Part/product: Корпус полипропилен  | designation М10-00.20.000-PP
    Материал: Полипропилен  ГОСТ 26996-86 (density 900 kg/m3)
    Масса: 4.96698
  - Component [assembly]: Обечайка  | designation М10-00.30.000  | pos. 1  | Материал: Полипропилен  ГОСТ 26996-86 (density 900 kg/m3); Масса: 0.647968; Раздел спецификации: Сборочные единицы; Форматы листов документа: A3; source file: М10-00.30.000 - Обечайка.a3d, М10-00.30.000 - Обечайка.cdw
  - Component [detail]: Фланец  | designation М5-00.10.002  | pos. 4  | Масса: 0.478225; Раздел спецификации: Детали; Форматы листов документа: A4; source file: ..\..\..\Магна ins 5\М5-00.00.000 - Насос Магна ins 5-C-N\3Д модель\М5-00.10.002 - Фланец.m3d, ..\..\..\Магна ins 5\М5-00.00.000 - Насос Магна ins 5-C-N\Чертежи\М5-00.10.002 - Фланец.cdw, D:\Magna\Магна Ins\Магна ins 5\М5-00.00.000 - Насос Магна ins 5-C-N\3Д модель\М5-00.10.002 - Фланец.m3d
  - Component [detail]: Колонна  | designation М10-00.25.001-PP  | pos. 6  | Масса: 1.63515; Раздел спецификации: Детали; Форматы листов документа: A4; source file: М10-00.25.001 - Колонна.cdw, М10-00.25.001 - Колонна.m3d
- Part/product: Корпус полипропилен 375 0,75кВт с разъёмной муфтой  | designation М10-00.20.000-PP-375-0,75кВт-M
    Материал: Полипропилен  ГОСТ 26996-86 (density 900 kg/m3)
    Масса: 5.65999
  - Component [detail]: Колонна  | designation М10-00.25.001-PP-375  | pos. 6  | Масса: 1.63515; Раздел спецификации: Детали; Форматы листов документа: A4; source file: М10-00.25.001 - Колонна.m3d
  - Component [detail]: Труба 32 PN10 S=2,9 FV PPR ф. "FV PLAST"  | pos. 12  | Материал: Труба 32 PN10 S=2,9 FV PPR ф. "FV PLAST" (density 0 kg/m3); Раздел спецификации: Материалы; Примечание: мм; source file: Труба 32 PN10 S=2,9 FV PPR ф. FV PLAST.m3d
  - Component [detail]: Колено 90@1~ @2~40FV PPR ф. "FV PLAST"  | pos. 9  | Масса: 0.141726; Раздел спецификации: Прочие изделия; source file: Колено 90гр 32 FV PPR ф. FV PLAST.m3d
  - Component [detail]: Плита опорная  | designation М10-00.20.001-01  | pos. 4  | Масса: 1.84628; Раздел спецификации: Детали; Форматы листов документа: A3; source file: М10-00.20.001 - Плита опорная.m3d
  - Component [assembly]: Обечайка  | designation М10-00.30.000  | pos. 1  | Материал: Полипропилен  ГОСТ 26996-86 (density 900 kg/m3); Масса: 0.647968; Раздел спецификации: Сборочные единицы; Форматы листов документа: A3; source file: М10-00.30.000 - Обечайка.a3d, М10-00.30.000 - Обечайка.cdw
  - Component [detail]: Фланец  | designation М10-00.20.002  | pos. 5
      Материал: Полипропилен  ГОСТ 26996-86 (density 900 kg/m3)
      Масса: 0.439491
      Раздел спецификации: Детали
      Форматы листов документа: A3
      Примечание: габ. 71, 80
      source file: М10-00.20.002 - Фланец.cdw, М10-00.20.002 - Фланец.m3d
  - Component [detail]: Муфта разъёмная 32  | pos. 7  | Масса: 0.949384; Раздел спецификации: Детали; source file: D:\1 ПКИ 3D\Полипропиленовые фитинги, трубы\Разборные муфты\Муфта разъёмная 32.m3d
- Part/product: Корпус полипропилен 375 1,1кВт  | designation М10-00.20.000-PP-375-1,1кВт
    Материал: Полипропилен  ГОСТ 26996-86 (density 900 kg/m3)
    Масса: 4.71061
  - Component [detail]: Фланец  | designation М10-00.20.002  | pos. 276
      Материал: Полипропилен  ГОСТ 26996-86 (density 900 kg/m3)
      Масса: 0.439491
      Раздел спецификации: Детали
      Форматы листов документа: A3
      Примечание: габ. 71, 80
      source file: М10-00.20.002 - Фланец.cdw, М10-00.20.002 - Фланец.m3d
  - Component [assembly]: Обечайка  | designation М10-00.30.000  | pos. 1  | Материал: Полипропилен  ГОСТ 26996-86 (density 900 kg/m3); Масса: 0.647968; Раздел спецификации: Сборочные единицы; Форматы листов документа: A3; source file: М10-00.30.000 - Обечайка.a3d, М10-00.30.000 - Обечайка.cdw
- Part/product: Корпус полипропилен 425 0,55кВт  | designation М10-00.20.000-PP-425-0,55кВт
    Материал: Полипропилен  ГОСТ 26996-86 (density 900 kg/m3)
    Масса: 5.21242
  - Component [assembly]: Обечайка  | designation М10-00.30.000  | pos. 1  | Материал: Полипропилен  ГОСТ 26996-86 (density 900 kg/m3); Масса: 0.647968; Раздел спецификации: Сборочные единицы; Форматы листов документа: A3; source file: М10-00.30.000 - Обечайка.a3d, М10-00.30.000 - Обечайка.cdw
  - Component [detail]: Фланец  | designation М5-00.10.002  | pos. 4  | Масса: 0.478225; Раздел спецификации: Детали; Форматы листов документа: A4; source file: D:\Magna\Магна Ins\Магна ins 5\М5-00.00.000 - Насос Магна ins 5-C-N\3Д модель\..\Чертежи\М5-00.10.002 - Фланец.cdw, D:\Magna\Магна Ins\Магна ins 5\М5-00.00.000 - Насос Магна ins 5-C-N\3Д модель\М5-00.10.002 - Фланец.m3d
- Part/product: Корпус полипропилен 425 0,75кВт  | designation М10-00.20.000-PP-425-0,75кВт
    Материал: Полипропилен  ГОСТ 26996-86 (density 900 kg/m3)
    Масса: 4.95604
  - Component [assembly]: Обечайка  | designation М10-00.30.000  | pos. 1  | Материал: Полипропилен  ГОСТ 26996-86 (density 900 kg/m3); Масса: 0.647968; Раздел спецификации: Сборочные единицы; Форматы листов документа: A3; source file: М10-00.30.000 - Обечайка.a3d, М10-00.30.000 - Обечайка.cdw
  - Component [detail]: Фланец  | designation М10-00.20.002  | pos. 287
      Материал: Полипропилен  ГОСТ 26996-86 (density 900 kg/m3)
      Масса: 0.439491
      Раздел спецификации: Детали
      Форматы листов документа: A3
      Примечание: габ. 71, 80
      source file: М10-00.20.002 - Фланец.cdw, М10-00.20.002 - Фланец.m3d
- Part/product: Корпус полипропилен 425 1,1кВт  | designation М10-00.20.000-PP-425-1,1кВт
    Материал: Полипропилен  ГОСТ 26996-86 (density 900 kg/m3)
    Масса: 4.95604
  - Component [assembly]: Обечайка  | designation М10-00.30.000  | pos. 1  | Материал: Полипропилен  ГОСТ 26996-86 (density 900 kg/m3); Масса: 0.647968; Раздел спецификации: Сборочные единицы; Форматы листов документа: A3; source file: М10-00.30.000 - Обечайка.a3d, М10-00.30.000 - Обечайка.cdw
  - Component [detail]: Фланец  | designation М10-00.20.002  | pos. 288
      Материал: Полипропилен  ГОСТ 26996-86 (density 900 kg/m3)
      Масса: 0.439491
      Раздел спецификации: Детали
      Форматы листов документа: A3
      Примечание: габ. 71, 80
      source file: М10-00.20.002 - Фланец.cdw, М10-00.20.002 - Фланец.m3d
- Part/product: Корпус полипропилен 425 0,55кВт с разъёмной муфтой  | designation М10-00.20.000-PP-425-0,55кВт-M
    Материал: Полипропилен  ГОСТ 26996-86 (density 900 kg/m3)
    Масса: 6.1618
  - Component [detail]: Колонна  | designation М10-00.25.001-PP-425  | pos. 6  | Масса: 1.88058; Раздел спецификации: Детали; Форматы листов документа: A4; source file: М10-00.25.001 - Колонна.m3d
  - Component [detail]: Труба 32 PN10 S=2,9 FV PPR ф. "FV PLAST"  | pos. 12  | Материал: Труба 32 PN10 S=2,9 FV PPR ф. "FV PLAST" (density 0 kg/m3); Раздел спецификации: Материалы; Примечание: мм; source file: Труба 32 PN10 S=2,9 FV PPR ф. FV PLAST.m3d
  - Component [detail]: Колено 90@1~ @2~40FV PPR ф. "FV PLAST"  | pos. 9  | Масса: 0.141726; Раздел спецификации: Прочие изделия; source file: Колено 90гр 32 FV PPR ф. FV PLAST.m3d
  - Component [detail]: Плита опорная  | designation М10-00.20.001  | pos. 5  | Масса: 2.06392; Раздел спецификации: Детали; Форматы листов документа: A3; source file: М10-00.20.001 - Плита опорная.m3d
  - Component [detail]: Фланец  | designation М5-00.10.002  | pos. 4  | Масса: 0.478225; Раздел спецификации: Детали; Форматы листов документа: A4; source file: D:\Magna\Магна Ins\Магна ins 5\М5-00.00.000 - Насос Магна ins 5-C-N\3Д модель\..\Чертежи\М5-00.10.002 - Фланец.cdw, D:\Magna\Магна Ins\Магна ins 5\М5-00.00.000 - Насос Магна ins 5-C-N\3Д модель\М5-00.10.002 - Фланец.m3d
  - Component [assembly]: Обечайка  | designation М10-00.30.000  | pos. 1  | Материал: Полипропилен  ГОСТ 26996-86 (density 900 kg/m3); Масса: 0.647968; Раздел спецификации: Сборочные единицы; Форматы листов документа: A3; source file: М10-00.30.000 - Обечайка.a3d, М10-00.30.000 - Обечайка.cdw
  - Component [detail]: Муфта разъёмная 32  | pos. 7  | Масса: 0.949384; Раздел спецификации: Детали; source file: D:\1 ПКИ 3D\Полипропиленовые фитинги, трубы\Разборные муфты\Муфта разъёмная 32.m3d
- Part/product: Корпус полипропилен 425 0,55кВт с резьбовым переходником  | designation М10-00.20.000-PP-425-0,55кВт-R
    Материал: Полипропилен  ГОСТ 26996-86 (density 900 kg/m3)
    Масса: 5.24529
  - Component [detail]: Колонна  | designation М10-00.25.001-PP-425  | pos. 6  | Масса: 1.88058; Раздел спецификации: Детали; Форматы листов документа: A4; source file: М10-00.25.001 - Колонна.m3d
  - Component [detail]: Труба 32 PN10 S=2,9 FV PPR ф. "FV PLAST"  | pos. 12  | Материал: Труба 32 PN10 S=2,9 FV PPR ф. "FV PLAST" (density 0 kg/m3); Раздел спецификации: Материалы; Примечание: мм; source file: Труба 32 PN10 S=2,9 FV PPR ф. FV PLAST.m3d
  - Component [detail]: Колено 90@1~ @2~40FV PPR ф. "FV PLAST"  | pos. 9  | Масса: 0.141726; Раздел спецификации: Прочие изделия; source file: Колено 90гр 32 FV PPR ф. FV PLAST.m3d
  - Component [detail]: Плита опорная  | designation М10-00.20.001  | pos. 5  | Масса: 2.06392; Раздел спецификации: Детали; Форматы листов документа: A3; source file: М10-00.20.001 - Плита опорная.m3d
  - Component [detail]: Фланец  | designation М5-00.10.002  | pos. 4  | Масса: 0.478225; Раздел спецификации: Детали; Форматы листов документа: A4; source file: D:\Magna\Магна Ins\Магна ins 5\М5-00.00.000 - Насос Магна ins 5-C-N\3Д модель\..\Чертежи\М5-00.10.002 - Фланец.cdw, D:\Magna\Магна Ins\Магна ins 5\М5-00.00.000 - Насос Магна ins 5-C-N\3Д модель\М5-00.10.002 - Фланец.m3d
  - Component [assembly]: Обечайка  | designation М10-00.30.000  | pos. 1  | Материал: Полипропилен  ГОСТ 26996-86 (density 900 kg/m3); Масса: 0.647968; Раздел спецификации: Сборочные единицы; Форматы листов документа: A3; source file: М10-00.30.000 - Обечайка.a3d, М10-00.30.000 - Обечайка.cdw
  - Component [detail]: Переходник с пластмассовой резьбой  / наружной 32х1" FV PPR  / ф. "FV PLAST"  | pos. 10  | Масса: 0.0328755; Раздел спецификации: Прочие изделия; source file: D:\1 ПКИ 3D\Полипропиленовые фитинги, трубы\Переходник с пластмассовой резьбой наружной 32х1 FV PPR ф.FV Plast.m3d
- Part/product: Корпус полипропилен 425 1,1кВт с разъёмной муфтой  | designation М10-00.20.000-PP-425-1,1кВт-M
    Материал: Полипропилен  ГОСТ 26996-86 (density 900 kg/m3)
    Масса: 5.90542
  - Component [detail]: Фланец  | designation М10-00.20.002  | pos. 5
      Материал: Полипропилен  ГОСТ 26996-86 (density 900 kg/m3)
      Масса: 0.439491
      Раздел спецификации: Детали
      Форматы листов документа: A3
      Примечание: габ. 71, 80
      source file: М10-00.20.002 - Фланец.cdw, М10-00.20.002 - Фланец.m3d
  - Component [detail]: Колонна  | designation М10-00.25.001-PP-425  | pos. 6  | Масса: 1.88058; Раздел спецификации: Детали; Форматы листов документа: A4; source file: М10-00.25.001 - Колонна.m3d
  - Component [detail]: Труба 32 PN10 S=2,9 FV PPR ф. "FV PLAST"  | pos. 12  | Материал: Труба 32 PN10 S=2,9 FV PPR ф. "FV PLAST" (density 0 kg/m3); Раздел спецификации: Материалы; Примечание: мм; source file: Труба 32 PN10 S=2,9 FV PPR ф. FV PLAST.m3d
  - Component [detail]: Колено 90@1~ @2~40FV PPR ф. "FV PLAST"  | pos. 9  | Масса: 0.141726; Раздел спецификации: Прочие изделия; source file: Колено 90гр 32 FV PPR ф. FV PLAST.m3d
  - Component [detail]: Плита опорная  | designation М10-00.20.001-01  | pos. 4  | Масса: 1.84628; Раздел спецификации: Детали; Форматы листов документа: A3; source file: М10-00.20.001 - Плита опорная.m3d
  - Component [assembly]: Обечайка  | designation М10-00.30.000  | pos. 1  | Материал: Полипропилен  ГОСТ 26996-86 (density 900 kg/m3); Масса: 0.647968; Раздел спецификации: Сборочные единицы; Форматы листов документа: A3; source file: М10-00.30.000 - Обечайка.a3d, М10-00.30.000 - Обечайка.cdw
  - Component [detail]: Муфта разъёмная 32  | pos. 7  | Масса: 0.949384; Раздел спецификации: Детали; source file: D:\1 ПКИ 3D\Полипропиленовые фитинги, трубы\Разборные муфты\Муфта разъёмная 32.m3d
- Part/product: Корпус полипропилен 425 1,1кВт с резьбовым переходником  | designation М10-00.20.000-PP-425-1,1кВт-R
    Материал: Полипропилен  ГОСТ 26996-86 (density 900 kg/m3)
    Масса: 4.98891
  - Component [detail]: Фланец  | designation М10-00.20.002  | pos. 5
      Материал: Полипропилен  ГОСТ 26996-86 (density 900 kg/m3)
      Масса: 0.439491
      Раздел спецификации: Детали
      Форматы листов документа: A3
      Примечание: габ. 71, 80
      source file: М10-00.20.002 - Фланец.cdw, М10-00.20.002 - Фланец.m3d
  - Component [detail]: Колонна  | designation М10-00.25.001-PP-425  | pos. 6  | Масса: 1.88058; Раздел спецификации: Детали; Форматы листов документа: A4; source file: М10-00.25.001 - Колонна.m3d
  - Component [detail]: Труба 32 PN10 S=2,9 FV PPR ф. "FV PLAST"  | pos. 12  | Материал: Труба 32 PN10 S=2,9 FV PPR ф. "FV PLAST" (density 0 kg/m3); Раздел спецификации: Материалы; Примечание: мм; source file: Труба 32 PN10 S=2,9 FV PPR ф. FV PLAST.m3d
  - Component [detail]: Колено 90@1~ @2~40FV PPR ф. "FV PLAST"  | pos. 9  | Масса: 0.141726; Раздел спецификации: Прочие изделия; source file: Колено 90гр 32 FV PPR ф. FV PLAST.m3d
  - Component [detail]: Плита опорная  | designation М10-00.20.001-01  | pos. 4  | Масса: 1.84628; Раздел спецификации: Детали; Форматы листов документа: A3; source file: М10-00.20.001 - Плита опорная.m3d
  - Component [assembly]: Обечайка  | designation М10-00.30.000  | pos. 1  | Материал: Полипропилен  ГОСТ 26996-86 (density 900 kg/m3); Масса: 0.647968; Раздел спецификации: Сборочные единицы; Форматы листов документа: A3; source file: М10-00.30.000 - Обечайка.a3d, М10-00.30.000 - Обечайка.cdw
  - Component [detail]: Переходник с пластмассовой резьбой  / наружной 32х1" FV PPR  / ф. "FV PLAST"  | pos. 10  | Масса: 0.0328755; Раздел спецификации: Прочие изделия; source file: D:\1 ПКИ 3D\Полипропиленовые фитинги, трубы\Переходник с пластмассовой резьбой наружной 32х1 FV PPR ф.FV Plast.m3d

Expressions: М10-00.25.001-PP-475; М10-00.25.001-PP-375; М10-00.25.001-PP-425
